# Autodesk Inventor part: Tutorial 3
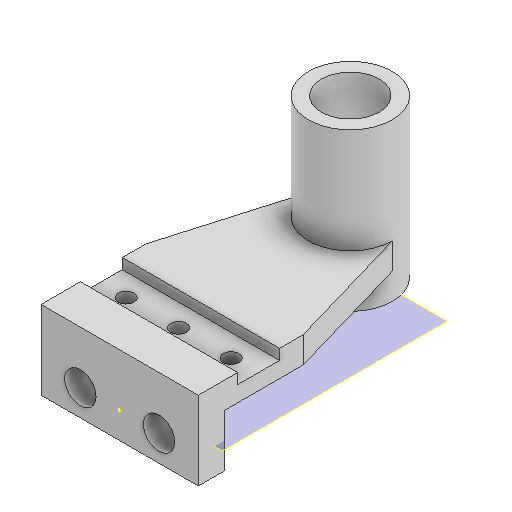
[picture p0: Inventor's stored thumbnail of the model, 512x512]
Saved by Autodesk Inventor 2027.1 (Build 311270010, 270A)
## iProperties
Created: 2021-03
Part Number: Tutorial 3
Material: Generic
Document SubType Name: Modeling
Designer: ASUS Laptop
Density: 1 g/cm^3
Appearance: Default
Author: ASUS Laptop
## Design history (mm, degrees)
sketch "Sketch1"
  geometry: L1 (0, 0)-(30, 0); L2 (30, 0)-(30, -15); L3 (30, -15)-(26, -15); L4 (26, -15)-(26, -31); L5 (26, -31)-(30, -31); L6 (30, -31)-(30, -40); L7 (20, -40)-(20, -10); L8 (20, -10)-(0, -10); L9 (0, -10)-(0, 0); L10 (20, -40)-(30, -40)
  constraints: 20 end point, 8 perpendicular, 1 horizontal, 1 parallel, 1 point on line
  dimensions: "d0" = 16 distance of L3.end L4.end; "d1" = 15 distance of L1.end L2.end; "d2" = 40 distance between parallel lines of L1 L10; "d3" = 30 distance between parallel lines of L9 L2; "d4" = 4 distance between parallel lines of L4 L2; "d5" = 10 distance between parallel lines of L8 L1
extrude "Extrusion1" new body sketch "Sketch1" stored distance "d6" = 60; taper "d7" = 0 deg
sketch "Sketch4"
  geometry: L1 (0, 9)-(60, 9) reference; L2 (0, 9)-(14, 57); L3 (14, 57)-(46, 57); L4 (46, 57)-(60, 9); L5 (60, 9)-(0, 9); L6 (30, -31)-(30, 84.04)
  constraints: 10 end point, 1 collinear, 1 parallel, 1 vertical, 1 other
  dimensions: "d8" = 32 distance of L2.end L3.end; "d9" = 48 distance between parallel lines of L3 L1
extrude "Extrusion2" join sketch "Sketch4" distance "d10" = 10; taper "d11" = 0 deg
workplane "Work Plane1"
sketch "Sketch5"
  geometry: L1 (14, -78)-(46, -78) reference; L2 (0, 0)-(0, 10) reference; C1 r 16 at (30, -78); 1 further point
  constraints: 1 centre point, 1 midpoint
  dimensions: "d13" = 32 diameter of C1; "d14" = 30 distance from line of L2 C1.centre
extrude "Extrusion3" join sketch "Sketch5" distance "d15" = 60; taper "d16" = 0 deg
sketch "Sketch6"
  geometry: L1 (-6.213, 7.5)-(70.808, 7.5); L2 (0, -15)-(60, -15) reference; L3 (0, 0)-(0, 16) reference; C1 r 3 at (10, 7.5); C2 r 3 at (30, 7.5); C3 r 3 at (50, 7.5); 1 further point
  constraints: 3 centre point, 3 point on line, 2 end point, 2 equal radius, 1 horizontal
  dimensions: "d17" = 22.5 distance between parallel lines of L2 L1; "d18" = 10 distance from line of C1.centre L3; "d19" = 20 distance of C2.centre C1.centre; "d20" = 20 distance of C3.centre C2.centre; "d21" = 6 diameter of C1
extrude "Extrusion4" cut sketch "Sketch6" distance "d22" = 60; taper "d23" = 0 deg
sketch "Sketch8"
  geometry: L1 (15, 10)-(52.331, 10); L2 (0, 0)-(60, 0) reference; L3 (0, 0)-(0, 30) reference; C1 r 6 at (15, 10); C2 r 6 at (45, 10); 1 further point
  constraints: 2 centre point, 2 end point, 1 equal radius, 1 horizontal, 1 point on line
  dimensions: "d24" = 10 distance between parallel lines of L2 L1; "d25" = 15 distance from line of L3 L1.start; "d26" = 30 distance of C2.centre L1.start; "d27" = 12 diameter of C2
extrude "Extrusion5" cut sketch "Sketch8" stored distance "d28" = 10; taper "d29" = 0 deg
sketch "Sketch9"
  geometry: C1 r 11 at (0, 0); A1 r 16 centre (0, 0) between (-16, 0) and (16, 0) reference; 1 further point
  constraints: 1 centre point, 1 coincident
  dimensions: "d30" = 11 radius of C1
extrude "Extrusion6" cut sketch "Sketch9" extent not by distance; stored distance "d31" = 0; taper "d32" = 0 deg
body "Solid1"
sketch "Sketch7"
  geometry: 1 further point
